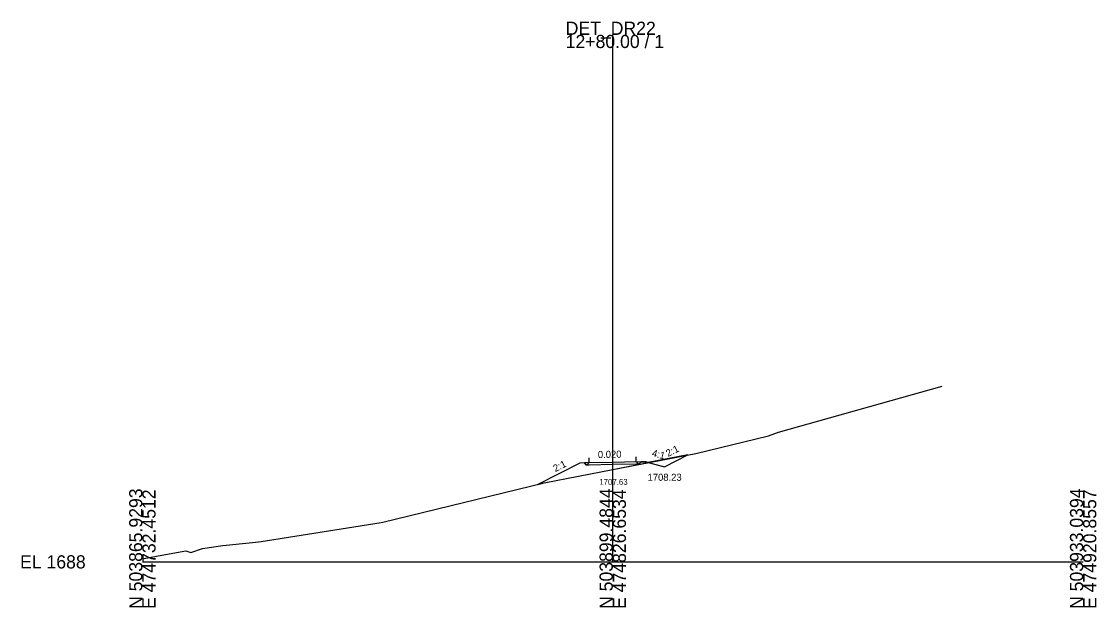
# Model space of a CAD drawing. Extents: x -26 to 1203, y -10 to 9633.
# Drawn here: x -25.7 to 202.8, y 6990.3 to 7114.8 of the extents above; entities that cross this region are included whole.
import ezdxf

# ---------------------------------------------------------------- set-up
doc = ezdxf.new("R2010")
doc.units = 0
for name, color, linetype in [('Exist Cross Section Cell', 7, 'Continuous'), ('Exist XS Center Line Elevation Label', 7, 'Continuous'), ('Exist XS Ground Line', 7, 'Continuous'), ('Prop XS Ditch Slope Text', 7, 'Continuous'), ('Prop XS Ditch Standard Text', 7, 'Continuous'), ('Prop XS Earthwork Shape', 7, 'Continuous'), ('Prop XS EOT Tick Mark', 7, 'Continuous'), ('Prop XS Finish Grade', 7, 'Continuous'), ('Prop XS Finish Grade Earthwork', 7, 'Continuous'), ('Prop XS Finish Grade Pavement', 7, 'Continuous'), ('Prop XS Pvmt Edge Slope', 7, 'Continuous'), ('Prop XS SE Text', 7, 'Continuous'), ('Prop XS Shoulder Borrow Shape', 7, 'Continuous'), ('Prop XS Side Slope Text', 7, 'Continuous'), ('Prop XS Subgrade Earthwork', 7, 'Continuous')]:
    doc.layers.add(name, color=color, linetype=linetype)

msp = doc.modelspace()

# ---------------------------------------------------------------- linework, layer by layer
at = {"layer": 'Exist Cross Section Cell'}
for p, q in [((100, 7000), (100, 7112)), ((0, 7000), (100, 7000)), ((100, 7000), (200, 7000))]:
    msp.add_line(p, q, dxfattribs=at)
at = {"layer": 'Exist XS Ground Line'}
msp.add_lwpolyline([(0, 7000.68), (3.34, 7001.31), (9.27, 7002.36), (10.31, 7002.01), (12.79, 7002.85), (17.1, 7003.51), (23.41, 7004.09), (24.69, 7004.28), (25.23, 7004.36), (50.77, 7008.38), (51.13, 7008.46), (85.42, 7016.81), (100, 7019.63), (117.67, 7023.05), (133.1, 7026.76), (135.24, 7027.57), (170.05, 7037.33)], dxfattribs=at)
at = {"layer": 'Prop XS Earthwork Shape'}
for points in [[(95, 7020.57), (94.45, 7020.56), (93.98, 7021.03), (93, 7020.95), (84.05, 7016.48), (85.42, 7016.81), (100, 7019.63), (107.55, 7021.09), (107, 7021.23), (106.02, 7021.27), (105.53, 7020.78), (105, 7020.77), (100, 7020.67)], [(107.55, 7021.09), (111, 7020.23), (115.98, 7022.72)]]:
    msp.add_lwpolyline(points, close=True, dxfattribs=at)
at = {"layer": 'Prop XS EOT Tick Mark'}
for p, q in [((95, 7021.11), (95, 7022.11)), ((105, 7021.31), (105, 7022.31))]:
    msp.add_line(p, q, dxfattribs=at)
at = {"layer": 'Prop XS Finish Grade'}
for p, q in [((95, 7021.11), (93.98, 7021.03)), ((105, 7021.31), (106.02, 7021.27))]:
    msp.add_line(p, q, dxfattribs=at)
at = {"layer": 'Prop XS Finish Grade Earthwork'}
for p, q in [((93, 7020.95), (84.05, 7016.48)), ((93.98, 7021.03), (93, 7020.95)), ((106.02, 7021.27), (107, 7021.23)), ((107, 7021.23), (111, 7020.23)), ((111, 7020.23), (115.98, 7022.72))]:
    msp.add_line(p, q, dxfattribs=at)
at = {"layer": 'Prop XS Finish Grade Pavement'}
for p, q in [((95, 7021.11), (100, 7021.21)), ((100, 7021.21), (105, 7021.31))]:
    msp.add_line(p, q, dxfattribs=at)
at = {"layer": 'Prop XS Pvmt Edge Slope'}
for p, q in [((95, 7021.11), (94.45, 7020.56)), ((105, 7021.31), (105.53, 7020.78))]:
    msp.add_line(p, q, dxfattribs=at)
at = {"layer": 'Prop XS Shoulder Borrow Shape'}
for points in [[(95, 7021.11), (93.98, 7021.03), (94.45, 7020.56)], [(105, 7021.31), (106.02, 7021.27), (105.53, 7020.78)]]:
    msp.add_lwpolyline(points, close=True, dxfattribs=at)
at = {"layer": 'Prop XS Subgrade Earthwork'}
for p, q in [((94.45, 7020.56), (93.98, 7021.03)), ((95, 7020.57), (94.45, 7020.56)), ((100, 7020.67), (95, 7020.57)), ((105, 7020.77), (100, 7020.67)), ((105, 7020.77), (105.53, 7020.78)), ((105.53, 7020.78), (106.02, 7021.27))]:
    msp.add_line(p, q, dxfattribs=at)

# ---------------------------------------------------------------- texts
at = {"layer": 'Exist Cross Section Cell'}
for s, p in [('DET_DR22', (90, 7112)), ('12+80.00 / 1', (90, 7109.2)), ('EL 1688', (-26, 6998.6))]:
    msp.add_text(s, height=2.8, dxfattribs=at).set_placement(p)
for s, p in [('N 503865.9293', (0, 6990)), ('E 474732.4512', (2.8, 6990)), ('N 503899.4844', (100, 6990)), ('E 474826.6534', (102.8, 6990)), ('N 503933.0394', (200, 6990)), ('E 474920.8557', (202.8, 6990))]:
    msp.add_text(s, height=2.8, rotation=90, dxfattribs=at).set_placement(p)
at = {"layer": 'Exist XS Center Line Elevation Label'}
msp.add_text('1707.63', height=1.25, dxfattribs=at).set_placement((97.13, 7016.38))
at = {"layer": 'Prop XS Ditch Slope Text'}
msp.add_text('4:1', height=1.5, rotation=345.9638, dxfattribs=at).set_placement((108.21, 7022.47))
at = {"layer": 'Prop XS Ditch Standard Text'}
msp.add_text('1708.23', height=1.5, dxfattribs=at).set_placement((107.4, 7017.23))
at = {"layer": 'Prop XS SE Text'}
msp.add_text('0.020', height=1.5, rotation=1.1458, dxfattribs=at).set_placement((96.85, 7022.06))
at = {"layer": 'Prop XS Side Slope Text'}
for p in [(111.76, 7022.29), (87.79, 7019.07)]:
    msp.add_text('2:1', height=1.5, rotation=26.5651, dxfattribs=at).set_placement(p)

doc.saveas('drawing.dxf')
